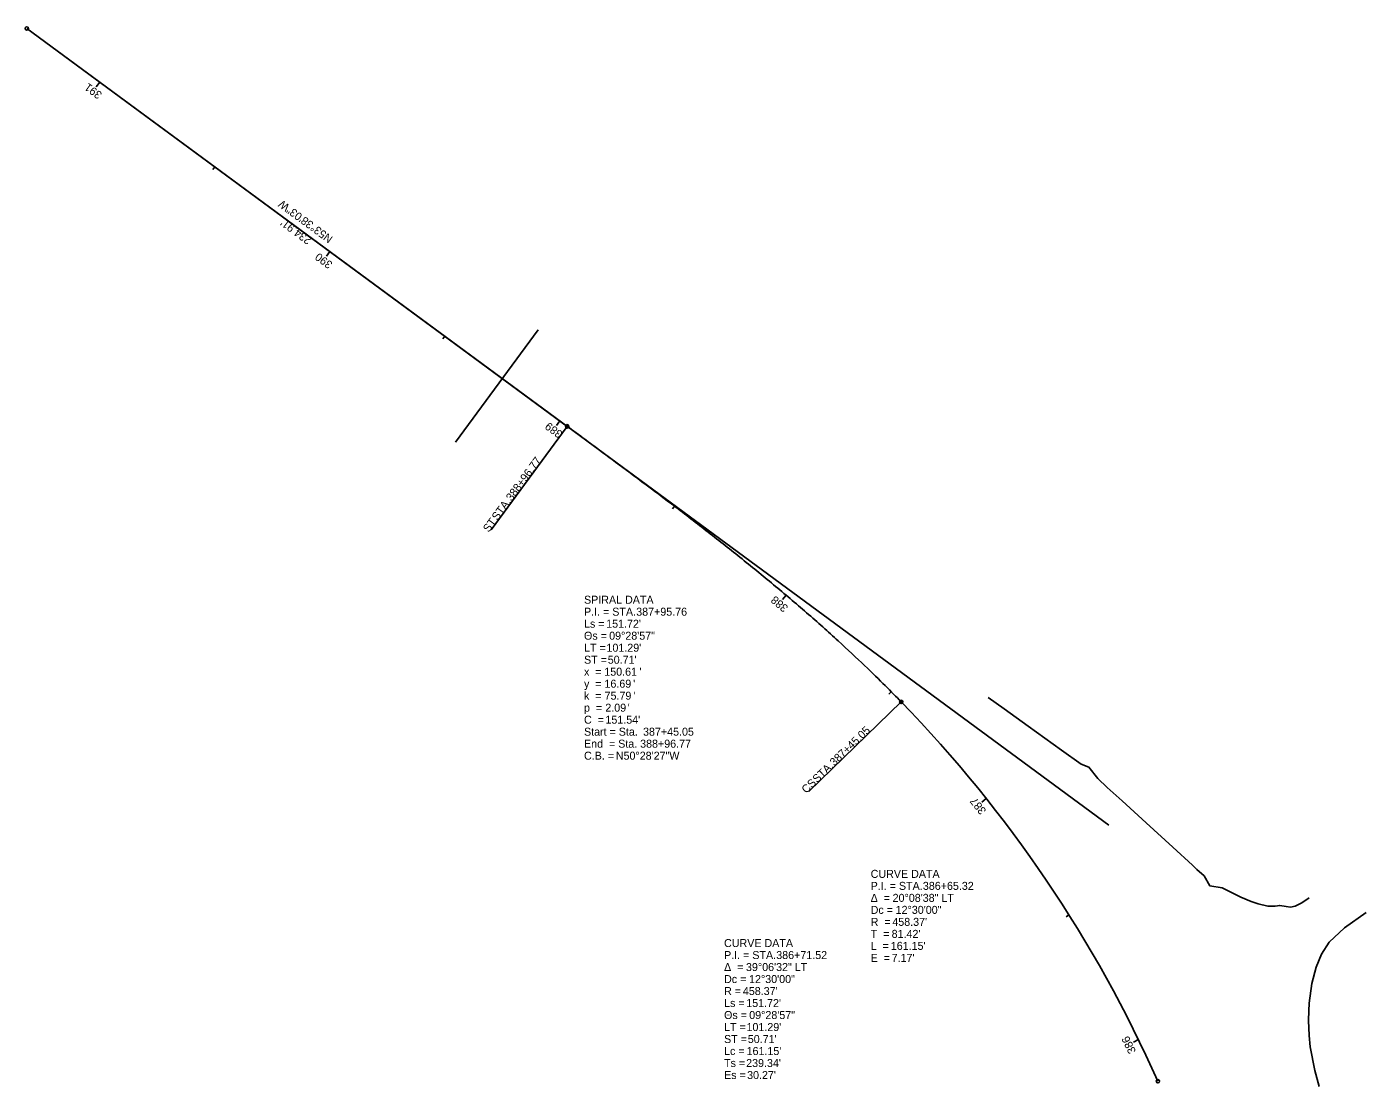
# Model space of a CAD drawing. Extents: x 111442 to 112326, y 429427 to 431077.
# Drawn here: x 111678.6 to 112147.4, y 430591.3 to 430960.4 of the extents above; entities that cross this region are included whole.
import ezdxf

# ---------------------------------------------------------------- set-up
doc = ezdxf.new("R2010")
doc.units = 0
for name, color, linetype in [('GE_P_Alignment', 7, 'Continuous'), ('GE_P_Alignment_100_Bearings', 7, 'Continuous'), ('GE_P_Alignment_100_Cardinal_Points', 7, 'Continuous'), ('GE_P_Alignment_100_Curve_Data', 7, 'Continuous'), ('GE_P_Alignment_100_Distances', 7, 'Continuous'), ('GE_P_Alignment_100_Stations', 7, 'Continuous'), ('SC_Scratch4', 7, 'Continuous'), ('SC_Scratch6', 7, 'Continuous')]:
    doc.layers.add(name, color=color, linetype=linetype)

msp = doc.modelspace()

# ---------------------------------------------------------------- linework, layer by layer
at = {"layer": 'GE_P_Alignment'}
for p in [(112057.32, 430680.88), (111867.73, 430820.49)]:
    msp.add_line(p, (111678.57, 430959.77), dxfattribs=at)
msp.add_arc((111655.73, 430404.76), 458.37, 24.0078, 44.1517, dxfattribs=at)
msp.add_arc((111655.73, 430404.76), 458.37, 24.0078, 44.1517, dxfattribs=at)
msp.add_open_spline([(111984.61, 430724.04), (111982.85, 430725.86), (111979.3, 430729.46), (111972.08, 430736.54), (111962.86, 430745.2), (111951.53, 430755.29), (111939.97, 430765.11), (111928.21, 430774.7), (111916.3, 430784.1), (111904.26, 430793.34), (111892.13, 430802.45), (111881.98, 430809.98), (111873.84, 430815.99), (111869.76, 430818.99), (111867.73, 430820.49)], degree=3, dxfattribs=at)
msp.add_open_spline([(111984.61, 430724.04), (111982.85, 430725.86), (111979.3, 430729.46), (111972.08, 430736.54), (111962.86, 430745.2), (111951.53, 430755.29), (111939.97, 430765.11), (111928.21, 430774.7), (111916.3, 430784.1), (111904.26, 430793.34), (111892.13, 430802.45), (111881.98, 430809.98), (111873.84, 430815.99), (111869.76, 430818.99), (111867.73, 430820.49)], degree=3, dxfattribs=at)
at = {"layer": 'GE_P_Alignment_100_Cardinal_Points'}
for p, q in [((111867.73, 430820.49), (111841.05, 430784.25)), ((111984.61, 430724.04), (111952.33, 430692.7))]:
    msp.add_line(p, q, dxfattribs=at)
for centre in [(111678.57, 430959.77), (111867.73, 430820.49), (111984.61, 430724.04), (112074.45, 430591.25)]:
    msp.add_circle(centre, 0.6, dxfattribs=at)
at = {"layer": 'GE_P_Alignment_100_Stations'}
for p, q in [((111704.08, 430940.99), (111702.89, 430939.38)), ((111744.34, 430911.34), (111743.63, 430910.37)), ((111784.61, 430881.69), (111783.42, 430880.08)), ((111824.87, 430852.05), (111824.16, 430851.08)), ((111865.13, 430822.4), (111863.94, 430820.79)), ((111905.25, 430792.56), (111904.52, 430791.6)), ((111944.33, 430761.38), (111943.04, 430759.86)), ((111981.15, 430727.58), (111980.3, 430726.73)), ((112014.36, 430690.23), (112012.79, 430688.98)), ((112043.3, 430649.49), (112042.29, 430648.85)), ((112067.64, 430605.84), (112065.85, 430604.97))]:
    msp.add_line(p, q, dxfattribs=at)
at = {"layer": 'SC_Scratch4'}
msp.add_line((111857.6, 430854.33), (111828.64, 430815), dxfattribs=at)
at = {"layer": 'SC_Scratch6'}
for points in [[(112127.38, 430655.44), (112124.86, 430653.65), (112122.53, 430652.53), (112120.84, 430652.19), (112119.36, 430652.4), (112117.09, 430652.81), (112115.47, 430652.53), (112112.92, 430652.54), (112109.5, 430653.31), (112107.04, 430654.17), (112103.52, 430655.64), (112099.5, 430657.61), (112096.96, 430658.99), (112092.65, 430659.64), (112090.63, 430663.17), (112088.13, 430665.33), (112086.51, 430666.91), (112079.66, 430673.17), (112070.31, 430681.71), (112061.9, 430689.4), (112056.72, 430694.13), (112053.39, 430697.17), (112050.29, 430701.24), (112047.62, 430702.29), (112040.76, 430707.18), (112029.1, 430715.51), (112020.63, 430721.56), (112014.99, 430725.58)], [(112147.36, 430650.28), (112139.8, 430644.92), (112134.43, 430639.93), (112131.73, 430635.76), (112129.85, 430631.21), (112128.37, 430625.5), (112127.44, 430618.63), (112127.27, 430615.87), (112127.2, 430612.47), (112127.37, 430607.23), (112127.78, 430603.31), (112129.39, 430595.01), (112130.93, 430589.43)]]:
    msp.add_lwpolyline(points, dxfattribs=at)

# ---------------------------------------------------------------- texts
at = {"layer": 'GE_P_Alignment_100_Bearings'}
msp.add_text('N53°38\'03"W', height=2.8, rotation=143.6341, dxfattribs=at).set_placement((111785.91, 430886.69))
at = {"layer": 'GE_P_Alignment_100_Cardinal_Points'}
for s, rotation, p in [('388+96.77', 53.6341, (111848.27, 430794.13)), (' STA. ', 53.6341, (111842.67, 430786.52)), ('ST', 53.6341, (111840.23, 430783.21)), ('387+45.05', 44.1517, (111961.23, 430701.4)), (' STA. ', 44.1517, (111954.44, 430694.82)), ('CS', 44.1517, (111951.36, 430691.82))]:
    msp.add_text(s, height=2.8, rotation=rotation, dxfattribs=at).set_placement(p)
at = {"layer": 'GE_P_Alignment_100_Curve_Data'}
for s, rotation, p in [('SPIRAL DATA', 359.9997, (111873.59, 430758.41)), ('P.I. = STA. ', 359.9997, (111873.59, 430754.21)), ('387+95.76', 359.9997, (111891.86, 430754.21)), ('Ls = ', 359.9997, (111873.59, 430750.01)), ("151.72'", 359.9997, (111881.35, 430750.01)), ('Θs = ', 359.9997, (111873.59, 430745.81)), ('09°28\'57"', 359.9997, (111882.39, 430745.81)), ('LT = ', 359.9997, (111873.59, 430741.61)), ("101.29'", 359.9997, (111881.45, 430741.61)), ('ST = ', 359.9997, (111873.59, 430737.41)), ("50.71'", 359.9997, (111881.9, 430737.41)), ('x  = ', 359.9997, (111873.59, 430733.21)), ('150.61', 359.9997, (111880.69, 430733.21)), ("'", 359.9997, (111892.98, 430733.21)), ('y  = ', 359.9997, (111873.59, 430729.01)), ('16.69', 359.9997, (111880.75, 430729.01)), ("'", 359.9997, (111890.81, 430729.01)), ('k  = ', 359.9997, (111873.59, 430724.81)), ('75.79', 359.9997, (111880.79, 430724.81)), ("'", 359.9997, (111890.84, 430724.81)), ('p  = ', 359.9997, (111873.59, 430720.61)), ('2.09', 359.9997, (111881.05, 430720.61)), ("'", 359.9997, (111888.87, 430720.61)), ('Start = Sta. ', 359.9997, (111873.59, 430712.21)), ('C  = ', 359.9997, (111873.59, 430716.41)), ("151.54'", 359.9997, (111881.09, 430716.41)), ('387+45.05', 359.9997, (111894.25, 430712.21)), ('End  = Sta. ', 359.9997, (111873.59, 430708.01)), ('388+96.77', 359.9997, (111893.23, 430708.01)), ('C.B. = ', 359.9997, (111873.59, 430703.81)), ('N50°28\'27"W', 359.9997, (111884.72, 430703.81)), ('CURVE DATA', 360, (111922.61, 430638.22)), ('P.I. = STA. ', 360, (111922.61, 430634.02)), ('386+71.52', 360, (111940.87, 430634.02)), ('Δ  = ', 360, (111922.61, 430629.82)), ('39°06\'32" LT', 360, (111930.28, 430629.82)), ('Dc = ', 360, (111922.61, 430625.62)), ('12°30\'00"', 360, (111931.35, 430625.62)), ('R = ', 360, (111922.61, 430621.42)), ("458.37'", 360, (111929.19, 430621.42)), ('Ls = ', 360, (111922.61, 430617.22)), ("151.72'", 360, (111930.37, 430617.22)), ('Θs = ', 360, (111922.61, 430613.02)), ('09°28\'57"', 360, (111931.41, 430613.02)), ('ST = ', 360, (111922.61, 430604.62)), ('LT = ', 360, (111922.61, 430608.82)), ("101.29'", 360, (111930.46, 430608.82)), ("50.71'", 360, (111930.91, 430604.62)), ('Lc = ', 360, (111922.61, 430600.42)), ("161.15'", 360, (111930.49, 430600.42)), ('Ts = ', 360, (111922.61, 430596.22)), ("239.34'", 360, (111930.34, 430596.22)), ('Es = ', 360, (111922.61, 430592.02)), ("30.27'", 360, (111930.67, 430592.02))]:
    msp.add_text(s, height=2.8, rotation=rotation, dxfattribs=at).set_placement(p)
for s, p in [('CURVE DATA', (111973.92, 430662.44)), ('P.I. = STA. ', (111973.92, 430658.24)), ('386+65.32', (111992.19, 430658.24)), ('Δ  = ', (111973.92, 430654.04)), ('20°08\'38" LT', (111981.6, 430654.04)), ('Dc = ', (111973.92, 430649.84)), ('12°30\'00"', (111982.66, 430649.84)), ('R  = ', (111973.92, 430645.64)), ("458.37'", (111981.5, 430645.64)), ('T  = ', (111973.92, 430641.44)), ('L  = ', (111973.92, 430637.24)), ("161.15'", (111980.96, 430637.24)), ("81.42'", (111981.26, 430641.44)), ('E  = ', (111973.92, 430633.04)), ("7.17'", (111981.26, 430633.04))]:
    msp.add_text(s, height=2.8, dxfattribs=at).set_placement(p)
at = {"layer": 'GE_P_Alignment_100_Distances'}
msp.add_text("234.91'", height=2.8, rotation=143.6341, dxfattribs=at).set_placement((111778.5, 430886.14))
at = {"layer": 'GE_P_Alignment_100_Stations'}
for s, rotation, p in [('391', 143.6341, (111705.14, 430937.11)), ('390', 143.6341, (111785.82, 430877.7)), ('389', 143.6341, (111866.32, 430818.42)), ('388', 139.7763, (111945.26, 430757.32)), ('387', 128.5201, (112014.53, 430686)), ('386', 116.0202, (112066.87, 430601.73))]:
    msp.add_text(s, height=2.8, rotation=rotation, dxfattribs=at).set_placement(p)

doc.saveas('drawing.dxf')
